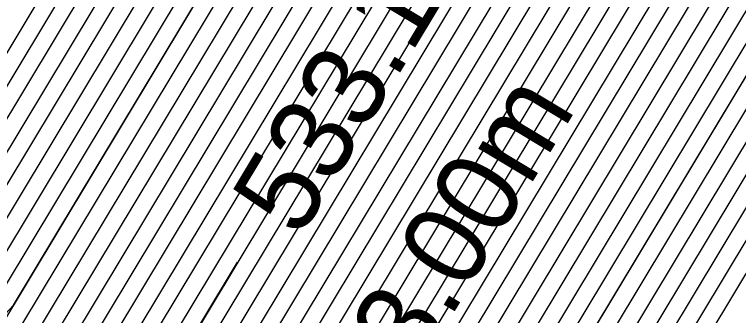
# Model space of a CAD drawing. Extents: x -866683 to -866410, y -1041951 to -1040252.
# Drawn here: x -866449.115 to -866446.498, y -1041939.494 to -1041938.404 of the extents above; entities that cross this region are included whole.
import ezdxf

# ---------------------------------------------------------------- set-up
doc = ezdxf.new("R2010")
doc.units = 0
for name, color, linetype in [('V-HL', 7, 'Continuous'), ('V-VEDL', 7, 'Continuous'), ('V_po_cm', 7, 'Continuous')]:
    doc.layers.add(name, color=color, linetype=linetype)

msp = doc.modelspace()

# ---------------------------------------------------------------- linework, layer by layer
at = {"layer": 'V-HL'}
msp.add_lwpolyline([(-866445.4083, -1041935.4466), (-866446.5113, -1041937.5028), (-866448.3992, -1041940.6448)], dxfattribs=at)
at = {"layer": 'V-VEDL'}
for points in [[(-866449.8962, -1041944.3286), (-866445.6181, -1041937.2089), (-866444.229, -1041934.6534), (-866443.5898, -1041933.1022), (-866443.7006, -1041932.5553), (-866443.7063, -1041931.5963), (-866443.6068, -1041930.2251), (-866443.4023, -1041928.4418), (-866443.8525, -1041926.8683), (-866444.9574, -1041925.5048), (-866446.7169, -1041924.3512), (-866448.0365, -1041923.6207), (-866448.9161, -1041923.3133), (-866449.7953, -1041923.5448)], [(-866449.7169, -1041924.4172), (-866449.1108, -1041924.2576), (-866448.5043, -1041924.4695), (-866447.5946, -1041924.9732), (-866446.3815, -1041925.7685), (-866445.6512, -1041926.9834), (-866445.4039, -1041928.6176), (-866445.6394, -1041930.6714), (-866445.7539, -1041932.2504), (-866445.7474, -1041933.3549), (-866445.6198, -1041933.9847), (-866446.0907, -1041935.3297), (-866447.16, -1041937.39), (-866450.4954, -1041942.9408)], [(-866450.4284, -1041941.6368), (-866447.8087, -1041937.2771), (-866446.9808, -1041935.6001), (-866446.6348, -1041934.426), (-866446.7708, -1041933.7547), (-866446.7777, -1041932.5775), (-866446.6557, -1041930.8945), (-866446.4047, -1041928.7056), (-866446.5506, -1041927.0409), (-866447.0935, -1041925.9004), (-866448.0334, -1041925.2842), (-866448.7383, -1041924.894), (-866449.2081, -1041924.7298), (-866449.6778, -1041924.8534)]]:
    msp.add_lwpolyline(points, dxfattribs=at)
at = {"layer": 'V_po_cm'}
for points in [[(-866449.0004, -1041943.5531), (-866444.9168, -1041936.7573), (-866443.5909, -1041934.3181), (-866442.9808, -1041932.8374), (-866443.0866, -1041932.3154), (-866443.092, -1041931.4), (-866442.9971, -1041930.0912), (-866442.8019, -1041928.389), (-866443.3129, -1041926.8338), (-866444.5301, -1041925.4257), (-866446.4536, -1041924.1646), (-866447.8961, -1041923.366), (-866448.8577, -1041923.03), (-866449.3382, -1041923.1565)], [(-866449.1497, -1041943.6824), (-866445.0337, -1041936.8326), (-866443.6973, -1041934.374), (-866443.0823, -1041932.8816), (-866443.1889, -1041932.3554), (-866443.1944, -1041931.4327), (-866443.0987, -1041930.1135), (-866442.9019, -1041928.3978), (-866443.4028, -1041926.8396), (-866444.6013, -1041925.4389), (-866446.4975, -1041924.1957), (-866447.9195, -1041923.4085), (-866448.8674, -1041923.0772), (-866449.3411, -1041923.2019)], [(-866449.299, -1041943.8116), (-866445.1506, -1041936.9079), (-866443.8036, -1041934.4299), (-866443.1838, -1041932.9257), (-866443.2912, -1041932.3954), (-866443.2967, -1041931.4654), (-866443.2003, -1041930.1358), (-866443.002, -1041928.4066), (-866443.4928, -1041926.8453), (-866444.6725, -1041925.4521), (-866446.5414, -1041924.2268), (-866447.9429, -1041923.4509), (-866448.8771, -1041923.1244), (-866449.344, -1041923.2474)], [(-866449.4483, -1041943.9409), (-866445.2675, -1041936.9831), (-866443.91, -1041934.4857), (-866443.2853, -1041932.9698), (-866443.3936, -1041932.4354), (-866443.3991, -1041931.4981), (-866443.302, -1041930.1582), (-866443.1021, -1041928.4154), (-866443.5827, -1041926.8511), (-866444.7437, -1041925.4653), (-866446.5853, -1041924.2579), (-866447.9663, -1041923.4934), (-866448.8869, -1041923.1717), (-866449.347, -1041923.2928)], [(-866449.3499, -1041923.3382), (-866448.8966, -1041923.2189), (-866447.9897, -1041923.5358), (-866446.6291, -1041924.289), (-866444.8149, -1041925.4784), (-866443.6726, -1041926.8568), (-866443.2022, -1041928.4242), (-866443.4036, -1041930.1805), (-866443.5015, -1041931.5309), (-866443.4959, -1041932.4753), (-866443.3868, -1041933.0139), (-866444.0163, -1041934.5416), (-866445.3844, -1041937.0584), (-866449.5976, -1041944.0701)], [(-866449.3528, -1041923.3836), (-866448.9063, -1041923.2661), (-866448.0131, -1041923.5782), (-866446.673, -1041924.3201), (-866444.8862, -1041925.4916), (-866443.7626, -1041926.8626), (-866443.3023, -1041928.433), (-866443.5052, -1041930.2028), (-866443.6039, -1041931.5636), (-866443.5983, -1041932.5153), (-866443.4883, -1041933.0581), (-866444.1226, -1041934.5975), (-866445.5012, -1041937.1337), (-866449.7469, -1041944.1993)], [(-866449.3586, -1041923.4745), (-866448.9258, -1041923.3605), (-866448.0599, -1041923.6631), (-866446.7608, -1041924.3823), (-866445.0286, -1041925.518), (-866443.9424, -1041926.8741), (-866443.5024, -1041928.4506), (-866443.7085, -1041930.2474), (-866443.8086, -1041931.629), (-866443.8029, -1041932.5953), (-866443.6913, -1041933.1463), (-866444.3353, -1041934.7093), (-866445.735, -1041937.2842), (-866450.0455, -1041944.4578)], [(-866449.3615, -1041923.5199), (-866448.9355, -1041923.4077), (-866448.0833, -1041923.7056), (-866446.8047, -1041924.4134), (-866445.0998, -1041925.5312), (-866444.0324, -1041926.8798), (-866443.6025, -1041928.4594), (-866443.8101, -1041930.2697), (-866443.911, -1041931.6617), (-866443.9053, -1041932.6353), (-866443.7928, -1041933.1904), (-866444.4417, -1041934.7652), (-866445.8519, -1041937.3594), (-866450.1949, -1041944.5871)], [(-866449.3644, -1041923.5653), (-866448.9453, -1041923.4549), (-866448.1067, -1041923.748), (-866446.8486, -1041924.4445), (-866445.171, -1041925.5444), (-866444.1223, -1041926.8856), (-866443.7026, -1041928.4681), (-866443.9117, -1041930.292), (-866444.0134, -1041931.6944), (-866444.0076, -1041932.6752), (-866443.8943, -1041933.2346), (-866444.548, -1041934.8211), (-866445.9687, -1041937.4347), (-866450.3442, -1041944.7163)], [(-866449.3673, -1041923.6107), (-866448.955, -1041923.5022), (-866448.13, -1041923.7905), (-866446.8924, -1041924.4756), (-866445.2422, -1041925.5576), (-866444.2122, -1041926.8913), (-866443.8026, -1041928.4769), (-866444.0134, -1041930.3143), (-866444.1158, -1041931.7271), (-866444.1099, -1041932.7152), (-866443.9958, -1041933.2787), (-866444.6544, -1041934.8769), (-866446.0856, -1041937.51), (-866450.4935, -1041944.8455)], [(-866449.911, -1041942.8643), (-866448.3914, -1041941.2281), (-866446.1869, -1041937.5593), (-866444.7555, -1041934.9242), (-866444.0973, -1041933.3228), (-866444.2123, -1041932.7552), (-866444.2182, -1041931.7598), (-866444.115, -1041930.3367), (-866443.9027, -1041928.4857), (-866444.3022, -1041926.8971), (-866445.3134, -1041925.5707), (-866446.9363, -1041924.5067), (-866448.1534, -1041923.8329), (-866448.9647, -1041923.5494), (-866449.3702, -1041923.6561)], [(-866449.9154, -1041942.7669), (-866448.4205, -1041941.1572), (-866446.2518, -1041937.548), (-866444.8445, -1041934.9512), (-866444.1988, -1041933.3669), (-866444.3146, -1041932.7952), (-866444.3206, -1041931.7925), (-866444.2166, -1041930.359), (-866444.0028, -1041928.4945), (-866444.3921, -1041926.9028), (-866445.3846, -1041925.5839), (-866446.9802, -1041924.5378), (-866448.1768, -1041923.8753), (-866448.9745, -1041923.5966), (-866449.3731, -1041923.7016)], [(-866449.376, -1041923.747), (-866448.9842, -1041923.6438), (-866448.2002, -1041923.9178), (-866447.0241, -1041924.5689), (-866445.4558, -1041925.5971), (-866444.4821, -1041926.9086), (-866444.1029, -1041928.5033), (-866444.3182, -1041930.3813), (-866444.4229, -1041931.8252), (-866444.417, -1041932.8352), (-866444.3003, -1041933.4111), (-866444.9335, -1041934.9782), (-866446.3166, -1041937.5367), (-866448.4496, -1041941.0864), (-866449.9198, -1041942.6695)], [(-866449.9242, -1041942.5721), (-866448.4787, -1041941.0155), (-866446.3815, -1041937.5254), (-866445.0226, -1041935.0053), (-866444.4018, -1041933.4552), (-866444.5193, -1041932.8751), (-866444.5253, -1041931.8579), (-866444.4199, -1041930.4036), (-866444.203, -1041928.5121), (-866444.572, -1041926.9143), (-866445.527, -1041925.6103), (-866447.068, -1041924.6), (-866448.2236, -1041923.9602), (-866448.9939, -1041923.691), (-866449.379, -1041923.7924)], [(-866449.9286, -1041942.4747), (-866448.5078, -1041940.9447), (-866446.4464, -1041937.5141), (-866445.1116, -1041935.0323), (-866444.5033, -1041933.4993), (-866444.6216, -1041932.9151), (-866444.6277, -1041931.8906), (-866444.5215, -1041930.4259), (-866444.303, -1041928.5209), (-866444.6619, -1041926.9201), (-866445.5982, -1041925.6235), (-866447.1119, -1041924.6311), (-866448.247, -1041924.0027), (-866449.0037, -1041923.7382), (-866449.3819, -1041923.8378)], [(-866449.9375, -1041942.2799), (-866448.5659, -1041940.803), (-866446.5761, -1041937.4915), (-866445.2896, -1041935.0864), (-866444.7063, -1041933.5876), (-866444.8263, -1041932.9951), (-866444.8325, -1041931.9561), (-866444.7248, -1041930.4705), (-866444.5032, -1041928.5385), (-866444.8418, -1041926.9316), (-866445.7406, -1041925.6499), (-866447.1996, -1041924.6933), (-866448.2938, -1041924.0876), (-866449.0232, -1041923.8327), (-866449.3877, -1041923.9286)], [(-866449.9419, -1041942.1825), (-866448.595, -1041940.7321), (-866446.641, -1041937.4802), (-866445.3786, -1041935.1134), (-866444.8078, -1041933.6317), (-866444.9287, -1041933.0351), (-866444.9349, -1041931.9888), (-866444.8264, -1041930.4929), (-866444.6033, -1041928.5473), (-866444.9317, -1041926.9374), (-866445.8118, -1041925.6631), (-866447.2435, -1041924.7244), (-866448.3172, -1041924.13), (-866449.0329, -1041923.8799), (-866449.3906, -1041923.9741)], [(-866449.9463, -1041942.0851), (-866448.6241, -1041940.6613), (-866446.7059, -1041937.469), (-866445.4676, -1041935.1405), (-866444.9093, -1041933.6758), (-866445.031, -1041933.075), (-866445.0372, -1041932.0215), (-866444.928, -1041930.5152), (-866444.7033, -1041928.5561), (-866445.0217, -1041926.9431), (-866445.883, -1041925.6762), (-866447.2874, -1041924.7555), (-866448.3406, -1041924.1724), (-866449.0426, -1041923.9271), (-866449.3935, -1041924.0195)], [(-866449.9507, -1041941.9877), (-866448.6532, -1041940.5905), (-866446.7707, -1041937.4577), (-866445.5566, -1041935.1675), (-866445.0108, -1041933.72), (-866445.1333, -1041933.115), (-866445.1396, -1041932.0542), (-866445.0297, -1041930.5375), (-866444.8034, -1041928.5649), (-866445.1116, -1041926.9489), (-866445.9542, -1041925.6894), (-866447.3313, -1041924.7866), (-866448.364, -1041924.2149), (-866449.0524, -1041923.9743), (-866449.3964, -1041924.0649)], [(-866449.3993, -1041924.1103), (-866449.0621, -1041924.0215), (-866448.3874, -1041924.2573), (-866447.3752, -1041924.8177), (-866446.0254, -1041925.7026), (-866445.2016, -1041926.9546), (-866444.9035, -1041928.5737), (-866445.1313, -1041930.5598), (-866445.242, -1041932.0869), (-866445.2357, -1041933.155), (-866445.1123, -1041933.7641), (-866445.6456, -1041935.1945), (-866446.8356, -1041937.4464), (-866448.6823, -1041940.5196), (-866449.9551, -1041941.8903)], [(-866449.9596, -1041941.7928), (-866448.7114, -1041940.4488), (-866446.9005, -1041937.4351), (-866445.7346, -1041935.2216), (-866445.2138, -1041933.8082), (-866445.338, -1041933.195), (-866445.3444, -1041932.1196), (-866445.2329, -1041930.5821), (-866445.0036, -1041928.5825), (-866445.2915, -1041926.9604), (-866446.0966, -1041925.7158), (-866447.419, -1041924.8488), (-866448.4108, -1041924.2998), (-866449.0718, -1041924.0688), (-866449.4022, -1041924.1557)], [(-866449.4051, -1041924.2012), (-866449.0816, -1041924.116), (-866448.4342, -1041924.3422), (-866447.4629, -1041924.8799), (-866446.1679, -1041925.729), (-866445.3814, -1041926.9661), (-866445.1037, -1041928.5912), (-866445.3345, -1041930.6044), (-866445.4468, -1041932.1523), (-866445.4404, -1041933.235), (-866445.3153, -1041933.8523), (-866445.8236, -1041935.2486), (-866446.9654, -1041937.4238), (-866448.7404, -1041940.3779), (-866449.964, -1041941.6954)], [(-866449.9684, -1041941.598), (-866448.7695, -1041940.3071), (-866447.0302, -1041937.4125), (-866445.9127, -1041935.2757), (-866445.4168, -1041933.8965), (-866445.5427, -1041933.2749), (-866445.5492, -1041932.185), (-866445.4362, -1041930.6267), (-866445.2037, -1041928.6), (-866445.4714, -1041926.9719), (-866446.2391, -1041925.7422), (-866447.5068, -1041924.911), (-866448.4576, -1041924.3847), (-866449.0913, -1041924.1632), (-866449.408, -1041924.2466)], [(-866449.4109, -1041924.292), (-866449.101, -1041924.2104), (-866448.4809, -1041924.4271), (-866447.5507, -1041924.9421), (-866446.3103, -1041925.7554), (-866445.5613, -1041926.9776), (-866445.3038, -1041928.6088), (-866445.5378, -1041930.649), (-866445.6515, -1041932.2177), (-866445.645, -1041933.3149), (-866445.5183, -1041933.9406), (-866446.0017, -1041935.3027), (-866447.0951, -1041937.4012), (-866448.7986, -1041940.2362), (-866449.9728, -1041941.5006)], [(-866449.1205, -1041924.3048), (-866448.5277, -1041924.512), (-866447.6385, -1041925.0043), (-866446.4527, -1041925.7817), (-866445.7412, -1041926.9891), (-866445.504, -1041928.6264), (-866445.7411, -1041930.6937), (-866445.8563, -1041932.2832), (-866445.8497, -1041933.3949), (-866445.7213, -1041934.0288), (-866446.1797, -1041935.3568), (-866447.2248, -1041937.3787), (-866448.8568, -1041940.0945), (-866449.9816, -1041941.3058)], [(-866449.9861, -1041941.2084), (-866448.8859, -1041940.0237), (-866447.2897, -1041937.3674), (-866446.2687, -1041935.3838), (-866445.8228, -1041934.073), (-866445.9521, -1041933.4349), (-866445.9587, -1041932.3159), (-866445.8427, -1041930.716), (-866445.6041, -1041928.6352), (-866445.8311, -1041926.9949), (-866446.5239, -1041925.7949), (-866447.6823, -1041925.0354), (-866448.5511, -1041924.5544), (-866449.1302, -1041924.352)], [(-866449.14, -1041924.3993), (-866448.5745, -1041924.5969), (-866447.7262, -1041925.0665), (-866446.5951, -1041925.8081), (-866445.9211, -1041927.0006), (-866445.7041, -1041928.644), (-866445.9443, -1041930.7383), (-866446.0611, -1041932.3486), (-866446.0544, -1041933.4748), (-866445.9243, -1041934.1171), (-866446.3577, -1041935.4108), (-866447.3546, -1041937.3561), (-866448.9149, -1041939.9529), (-866449.9905, -1041941.111)], [(-866449.9949, -1041941.0136), (-866448.944, -1041939.882), (-866447.4195, -1041937.3448), (-866446.4467, -1041935.4379), (-866446.0258, -1041934.1612), (-866446.1567, -1041933.5148), (-866446.1634, -1041932.3813), (-866446.0459, -1041930.7606), (-866445.8042, -1041928.6528), (-866446.011, -1041927.0064), (-866446.6663, -1041925.8213), (-866447.7701, -1041925.0976), (-866448.5979, -1041924.6393), (-866449.1497, -1041924.4465)], [(-866449.1594, -1041924.4937), (-866448.6213, -1041924.6818), (-866447.814, -1041925.1287), (-866446.7375, -1041925.8345), (-866446.1009, -1041927.0121), (-866445.9043, -1041928.6616), (-866446.1476, -1041930.7829), (-866446.2658, -1041932.414), (-866446.2591, -1041933.5548), (-866446.1273, -1041934.2053), (-866446.5357, -1041935.4649), (-866447.4843, -1041937.3335), (-866448.9731, -1041939.8112), (-866449.9993, -1041940.9162)], [(-866449.1692, -1041924.5409), (-866448.6447, -1041924.7242), (-866447.8579, -1041925.1598), (-866446.8087, -1041925.8477), (-866446.1909, -1041927.0179), (-866446.0044, -1041928.6704), (-866446.2492, -1041930.8052), (-866446.3682, -1041932.4467), (-866446.3614, -1041933.5948), (-866446.2288, -1041934.2495), (-866446.6247, -1041935.492), (-866447.5492, -1041937.3222), (-866449.0022, -1041939.7403), (-866450.0037, -1041940.8188)], [(-866449.1789, -1041924.5881), (-866448.6681, -1041924.7666), (-866447.9018, -1041925.1909), (-866446.8799, -1041925.8608), (-866446.2808, -1041927.0236), (-866446.1044, -1041928.6792), (-866446.3508, -1041930.8275), (-866446.4706, -1041932.4794), (-866446.4638, -1041933.6348), (-866446.3303, -1041934.2936), (-866446.7138, -1041935.519), (-866447.6141, -1041937.3109), (-866449.0313, -1041939.6695), (-866450.0081, -1041940.7214)], [(-866449.1886, -1041924.6353), (-866448.6915, -1041924.8091), (-866447.9456, -1041925.222), (-866446.9511, -1041925.874), (-866446.3707, -1041927.0294), (-866446.2045, -1041928.688), (-866446.4525, -1041930.8499), (-866446.573, -1041932.5121), (-866446.5661, -1041933.6747), (-866446.4318, -1041934.3377), (-866446.8028, -1041935.546), (-866447.6789, -1041937.2997), (-866449.0604, -1041939.5986), (-866450.0125, -1041940.6239)], [(-866449.1984, -1041924.6826), (-866448.7149, -1041924.8515), (-866447.9895, -1041925.2531), (-866447.0223, -1041925.8872), (-866446.4607, -1041927.0351), (-866446.3046, -1041928.6968), (-866446.5541, -1041930.8722), (-866446.6754, -1041932.5448), (-866446.6684, -1041933.7147), (-866446.5333, -1041934.3818), (-866446.8918, -1041935.5731), (-866447.7438, -1041937.2884), (-866449.0895, -1041939.5278), (-866450.017, -1041940.5265)], [(-866449.1476, -1041939.3861), (-866447.8736, -1041937.2658), (-866447.0698, -1041935.6271), (-866446.7363, -1041934.4701), (-866446.8731, -1041933.7947), (-866446.8801, -1041932.6102), (-866446.7573, -1041930.9168), (-866446.5048, -1041928.7143), (-866446.6406, -1041927.0466), (-866447.1647, -1041925.9136), (-866448.0773, -1041925.3153), (-866448.7617, -1041924.9364), (-866449.2179, -1041924.777)], [(-866449.1767, -1041939.3152), (-866447.9384, -1041937.2545), (-866447.1588, -1041935.6542), (-866446.8378, -1041934.5142), (-866446.9755, -1041933.8347), (-866446.9825, -1041932.6429), (-866446.859, -1041930.9391), (-866446.6048, -1041928.7231), (-866446.7305, -1041927.0524), (-866447.2359, -1041925.9268), (-866448.1212, -1041925.3464), (-866448.7851, -1041924.9789), (-866449.2276, -1041924.8242)], [(-866449.2058, -1041939.2444), (-866448.0033, -1041937.2432), (-866447.2478, -1041935.6812), (-866446.9393, -1041934.5583), (-866447.0778, -1041933.8746), (-866447.0849, -1041932.6757), (-866446.9606, -1041930.9614), (-866446.7049, -1041928.7319), (-866446.8204, -1041927.0581), (-866447.3071, -1041925.94), (-866448.1651, -1041925.3775), (-866448.8085, -1041925.0213), (-866449.2373, -1041924.8714)], [(-866449.2349, -1041939.1736), (-866448.0682, -1041937.2319), (-866447.3368, -1041935.7082), (-866447.0408, -1041934.6025), (-866447.1801, -1041933.9146), (-866447.1873, -1041932.7084), (-866447.0622, -1041930.9837), (-866446.805, -1041928.7407), (-866446.9104, -1041927.0639), (-866447.3783, -1041925.9531), (-866448.2089, -1041925.4086), (-866448.8318, -1041925.0637), (-866449.2471, -1041924.9186)], [(-866449.2568, -1041924.9659), (-866448.8552, -1041925.1062), (-866448.2528, -1041925.4397), (-866447.4496, -1041925.9663), (-866447.0003, -1041927.0696), (-866446.9051, -1041928.7495), (-866447.1639, -1041931.0061), (-866447.2897, -1041932.7411), (-866447.2825, -1041933.9546), (-866447.1423, -1041934.6466), (-866447.4258, -1041935.7353), (-866448.133, -1041937.2207), (-866449.264, -1041939.1027)], [(-866449.293, -1041939.0319), (-866448.1979, -1041937.2094), (-866447.5148, -1041935.7623), (-866447.2438, -1041934.6907), (-866447.3848, -1041933.9946), (-866447.392, -1041932.7738), (-866447.2655, -1041931.0284), (-866447.0051, -1041928.7583), (-866447.0902, -1041927.0754), (-866447.5208, -1041925.9795), (-866448.2967, -1041925.4708), (-866448.8786, -1041925.1486), (-866449.2665, -1041925.0131)], [(-866449.2763, -1041925.0603), (-866448.902, -1041925.1911), (-866448.3406, -1041925.5019), (-866447.592, -1041925.9927), (-866447.1802, -1041927.0811), (-866447.1052, -1041928.7671), (-866447.3671, -1041931.0507), (-866447.4944, -1041932.8065), (-866447.4872, -1041934.0345), (-866447.3453, -1041934.7348), (-866447.6039, -1041935.7894), (-866448.2628, -1041937.1981), (-866449.3221, -1041938.961)], [(-866449.3512, -1041938.8902), (-866448.3277, -1041937.1868), (-866447.6929, -1041935.8164), (-866447.4468, -1041934.779), (-866447.5895, -1041934.0745), (-866447.5968, -1041932.8392), (-866447.4687, -1041931.073), (-866447.2053, -1041928.7759), (-866447.2701, -1041927.0869), (-866447.6632, -1041926.0059), (-866448.3845, -1041925.533), (-866448.9254, -1041925.2335), (-866449.286, -1041925.1075)], [(-866447.733, -1041940.7285), (-866445.6181, -1041937.2089), (-866445.5733, -1041937.1265)], [(-866450.5329, -1041939.9393), (-866450.5172, -1041940.1937), (-866450.0214, -1041940.4291), (-866449.1185, -1041939.4569), (-866448.0543, -1041937.6858)], [(-866450.6579, -1041940.3021), (-866450.6085, -1041941.1034), (-866449.9772, -1041941.4032), (-866448.8277, -1041940.1654), (-866448.3086, -1041939.3014)]]:
    msp.add_lwpolyline(points, dxfattribs=at)

# ---------------------------------------------------------------- texts
for s, p in [('533.10m', (-866448.0842, -1041939.2193)), ('533.00m', (-866447.8871, -1041940.0838))]:
    msp.add_text(s, height=0.3, rotation=58.9988, dxfattribs=at).set_placement(p)

doc.saveas('drawing.dxf')
